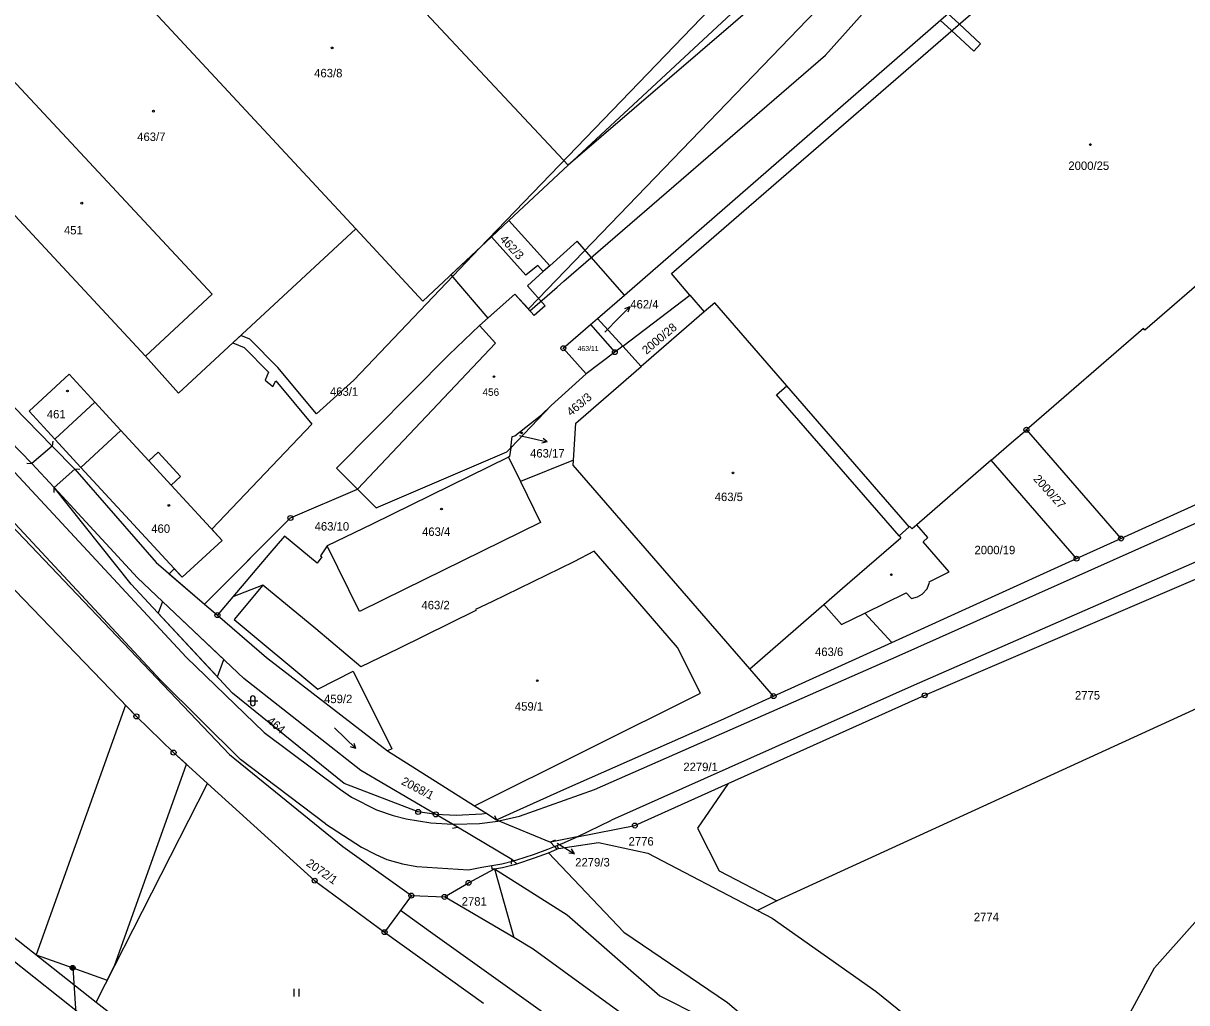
# Model space of a CAD drawing. Extents: x -504988 to -494607, y -1123820 to -1114018.
# Drawn here: x -496720.6 to -496486.2, y -1120850 to -1120652.7 of the extents above; entities that cross this region are included whole.
import ezdxf

# ---------------------------------------------------------------- set-up
doc = ezdxf.new("R2010")
doc.units = 0
for name, color, linetype in [('Hranice parcel', 7, 'Continuous'), ('Parcelní čísla', 7, 'Continuous'), ('Pop  PČ popisy', 7, 'Continuous'), ('Poz předměty', 7, 'Continuous'), ('Vnitřní kresba', 7, 'Continuous'), ('Věcná břemena k části', 7, 'Continuous'), ('Značky bodu BP', 7, 'Continuous'), ('Značky budov', 7, 'Continuous'), ('Značky kultur', 7, 'Continuous')]:
    doc.layers.add(name, color=color, linetype=linetype)

msp = doc.modelspace()

# ---------------------------------------------------------------- linework, layer by layer
at = {"layer": 'Hranice parcel'}
for p, q in [((-496599.45, -1120707.48), (-496501, -1120621.83)), ((-496610.77, -1120681.32), (-496661.37, -1120627.12)), ((-496736.91, -1120675.79), (-496695.94, -1120719.79)), ((-496610.77, -1120681.32), (-496622.74, -1120692.49)), ((-496622.74, -1120692.49), (-496626.2, -1120695.72)), ((-496622.74, -1120692.49), (-496614.48, -1120701.58)), ((-496640.08, -1120708.68), (-496653.59, -1120694.16)), ((-496626.2, -1120695.72), (-496640.08, -1120708.68)), ((-496614.48, -1120701.58), (-496615.79, -1120702.76)), ((-496604.86, -1120712.18), (-496599.45, -1120707.48)), ((-496599.79, -1120717.77), (-496586.26, -1120707.47)), ((-496586.26, -1120707.47), (-496583.37, -1120710.85)), ((-496583.37, -1120710.85), (-496596.06, -1120721.88)), ((-496606.31, -1120713.44), (-496604.86, -1120712.18)), ((-496606.31, -1120713.44), (-496601.38, -1120718.98)), ((-496599.79, -1120717.77), (-496604.86, -1120712.18)), ((-496601.38, -1120718.98), (-496607.13, -1120723.35)), ((-496599.79, -1120717.77), (-496601.38, -1120718.98)), ((-496596.06, -1120721.88), (-496599.79, -1120717.77)), ((-496614.22, -1120729.7), (-496607.13, -1120723.35)), ((-496542.87, -1120753.23), (-496566.72, -1120725.75)), ((-496614.22, -1120729.7), (-496622.37, -1120738.24)), ((-496616.13, -1120731.58), (-496614.22, -1120729.7)), ((-496499.4, -1120756.52), (-496439.9, -1120729.53)), ((-496700.9, -1120734.76), (-496708.96, -1120742.19)), ((-496521.45, -1120737.2), (-496518.46, -1120734.61)), ((-496518.46, -1120734.61), (-496499.4, -1120756.52)), ((-496714.72, -1120737.91), (-496710.16, -1120742.53)), ((-496525.56, -1120740.76), (-496521.45, -1120737.2)), ((-496622.62, -1120740.01), (-496622.79, -1120740.14)), ((-496622.79, -1120740.14), (-496620.39, -1120745.03)), ((-496622.37, -1120738.24), (-496622.62, -1120740.01)), ((-496714.32, -1120746.22), (-496718.88, -1120741.41)), ((-496609.72, -1120740.74), (-496620.39, -1120745.03)), ((-496525.56, -1120740.76), (-496540.53, -1120753.75)), ((-496508.34, -1120760.57), (-496525.56, -1120740.76)), ((-496508.34, -1120760.57), (-496499.4, -1120756.52)), ((-496652.84, -1120771.24), (-496659.35, -1120757.98)), ((-496670.9, -1120759.46), (-496678.32, -1120768.24)), ((-496545.59, -1120777.46), (-496508.34, -1120760.57)), ((-496672.33, -1120765.9), (-496678.32, -1120768.24)), ((-496678.32, -1120768.24), (-496680.54, -1120770.86)), ((-496435.15, -1120768.26), (-496568.75, -1120829.51)), ((-496550.98, -1120771.52), (-496542.65, -1120767.47)), ((-496684.03, -1120769.74), (-496681.46, -1120771.94)), ((-496574.21, -1120782.75), (-496559.3, -1120769.81)), ((-496559.3, -1120769.81), (-496555.71, -1120773.83)), ((-496680.54, -1120770.86), (-496681.46, -1120771.94)), ((-496555.71, -1120773.83), (-496550.98, -1120771.52)), ((-496545.59, -1120777.46), (-496550.98, -1120771.52)), ((-496569.39, -1120788.25), (-496545.59, -1120777.46)), ((-496569.39, -1120788.25), (-496574.21, -1120782.75)), ((-496647.2, -1120799.29), (-496629.63, -1120810.34)), ((-496705.9, -1120849.89), (-496683.43, -1120805.87)), ((-496760.7, -1120806.72), (-496705.9, -1120849.89)), ((-496622.14, -1120821.13), (-496633.09, -1120814.63)), ((-496608.94, -1120816.59), (-496614.32, -1120817.64)), ((-496614.74, -1120819.84), (-496613.04, -1120819.11)), ((-496613.04, -1120819.11), (-496612.72, -1120818.97)), ((-496625.66, -1120823.04), (-496621.76, -1120836.9)), ((-496642.38, -1120828.43), (-496647.77, -1120835.8)), ((-496642.38, -1120828.43), (-496635.69, -1120828.69)), ((-496621.76, -1120836.9), (-496635.69, -1120828.69)), ((-496568.75, -1120829.51), (-496572.66, -1120831.42)), ((-496647.77, -1120835.8), (-496627.83, -1120850.13))]:
    msp.add_line(p, q, dxfattribs=at)
for points in [[(-496576.2, -1120593.19), (-496572.35, -1120597.31), (-496590.77, -1120614.56), (-496589.81, -1120615.63), (-496589.91, -1120619.17), (-496586.4, -1120619.3), (-496583.79, -1120622.09), (-496583.86, -1120625.64), (-496580.35, -1120625.77), (-496577.76, -1120628.55), (-496577.86, -1120632.04), (-496574.29, -1120632.22), (-496566.73, -1120640.34), (-496610.77, -1120681.32)], [(-496653.59, -1120694.16), (-496706.72, -1120636.91), (-496707.61, -1120635.95)], [(-496586.26, -1120707.47), (-496589.96, -1120703.15), (-496514.17, -1120637.38), (-496507.54, -1120645.06)], [(-496718.88, -1120741.41), (-496755.05, -1120704.18), (-496797.4, -1120658.11)], [(-496789.1, -1120656), (-496791.3, -1120657.18), (-496753.93, -1120697.83), (-496714.72, -1120737.91)], [(-496695.94, -1120719.79), (-496682.54, -1120707.31), (-496723.77, -1120663.04), (-496737.17, -1120675.52)], [(-496467.67, -1120691.18), (-496480.14, -1120702.04), (-496494.59, -1120714.52), (-496494.88, -1120714.19), (-496518.46, -1120734.61)], [(-496653.59, -1120694.16), (-496689.31, -1120727.24), (-496695.94, -1120719.79)], [(-496615.79, -1120702.76), (-496616.91, -1120701.5), (-496619.32, -1120703.46), (-496626.2, -1120695.72)], [(-496599.45, -1120707.48), (-496608.97, -1120696.64), (-496614.48, -1120701.58)], [(-496615.79, -1120702.76), (-496619.01, -1120705.64), (-496615.45, -1120709.66), (-496617.64, -1120711.6)], [(-496617.64, -1120711.6), (-496621.52, -1120707.27), (-496628.62, -1120713.63), (-496634.8, -1120719.53)], [(-496566.72, -1120725.75), (-496581.25, -1120709.01), (-496583.37, -1120710.85)], [(-496607.13, -1120723.35), (-496611.76, -1120718.18), (-496606.31, -1120713.44)], [(-496634.8, -1120719.53), (-496657.48, -1120742.36), (-496653.26, -1120746.55)], [(-496700.9, -1120734.76), (-496706.13, -1120729.08), (-496711.34, -1120723.42), (-496719.41, -1120730.83), (-496714.19, -1120736.5), (-496708.96, -1120742.19)], [(-496609.72, -1120740.74), (-496609.21, -1120733.31), (-496596.06, -1120721.88)], [(-496622.37, -1120738.24), (-496622.04, -1120735.94), (-496621.53, -1120735.81), (-496616.13, -1120731.58)], [(-496680.53, -1120756.9), (-496690.8, -1120745.74), (-496688.91, -1120743.99), (-496693.41, -1120739.14), (-496695.27, -1120740.87), (-496700.9, -1120734.76)], [(-496736.43, -1120739.78), (-496679.03, -1120800.02), (-496656.16, -1120818.53), (-496642.38, -1120828.43)], [(-496622.79, -1120740.14), (-496650.3, -1120753.65), (-496659.35, -1120757.98)], [(-496653.26, -1120746.55), (-496649.47, -1120750.31), (-496623.13, -1120739.04), (-496622.37, -1120738.24)], [(-496710.16, -1120742.53), (-496693.8, -1120761.35), (-496684.03, -1120769.74)], [(-496708.96, -1120742.19), (-496688.59, -1120764.32), (-496680.53, -1120756.9)], [(-496574.21, -1120782.75), (-496609.79, -1120741.73), (-496609.72, -1120740.74)], [(-496578.55, -1120805.88), (-496538.95, -1120788.09), (-496442.52, -1120746.8), (-496429.62, -1120741.25)], [(-496637.46, -1120812.08), (-496652.57, -1120803.23), (-496676.15, -1120784.7), (-496697.59, -1120764.44), (-496714.32, -1120746.22)], [(-496637.46, -1120812.08), (-496637.86, -1120812.05), (-496641.01, -1120811.58), (-496655.93, -1120805.84), (-496678.43, -1120787.63), (-496698.84, -1120765.71), (-496714.32, -1120746.22)], [(-496684.03, -1120769.74), (-496682.96, -1120768.68), (-496666.75, -1120752.38), (-496653.26, -1120746.55)], [(-496620.39, -1120745.03), (-496616.33, -1120753.28), (-496643.83, -1120766.78), (-496652.84, -1120771.24)], [(-496541.92, -1120754.06), (-496542.05, -1120754.17), (-496542.87, -1120753.23)], [(-496542.65, -1120767.47), (-496541.63, -1120768.59), (-496540.41, -1120768.28), (-496539.43, -1120767.7), (-496538.48, -1120766.62), (-496537.97, -1120765.39), (-496538.07, -1120765.22), (-496533.99, -1120763.22), (-496539.27, -1120757.16), (-496538.29, -1120756.33), (-496540.53, -1120753.75)], [(-496540.53, -1120753.75), (-496541.48, -1120754.58), (-496541.92, -1120754.06)], [(-496659.35, -1120757.98), (-496660.68, -1120759.98), (-496660.4, -1120760.21), (-496661.37, -1120761.45), (-496667.95, -1120756.02), (-496670.9, -1120759.46)], [(-496730.97, -1120757.93), (-496725.74, -1120763.35), (-496697.78, -1120792.34), (-496690.3, -1120799.63), (-496683.43, -1120805.87)], [(-496629.63, -1120810.34), (-496584.12, -1120787.67), (-496588.73, -1120778.45), (-496595.45, -1120770.65), (-496605.54, -1120759.06), (-496609.63, -1120761.18), (-496626.17, -1120769.27), (-496629.46, -1120770.83), (-496629.38, -1120771.01), (-496645.05, -1120778.75), (-496652.55, -1120782.38), (-496661.64, -1120774.72), (-496672.33, -1120765.9)], [(-496672.33, -1120765.9), (-496678.08, -1120772.84), (-496661.22, -1120786.83), (-496654.09, -1120783.25), (-496646.34, -1120798.86), (-496647.2, -1120799.29)], [(-496681.46, -1120771.94), (-496671.55, -1120780.45), (-496647.2, -1120799.29)], [(-496572.66, -1120831.42), (-496569.68, -1120832.98), (-496548.73, -1120847.78), (-496521.28, -1120869.97), (-496513.63, -1120873.99), (-496508.49, -1120871.39), (-496505.53, -1120866.79), (-496492.64, -1120843.01), (-496469.33, -1120816.78), (-496459.79, -1120808.55), (-496450.03, -1120793.69), (-496441, -1120785.01)], [(-496625.22, -1120813.19), (-496611.64, -1120807.04), (-496580.04, -1120793.08), (-496569.39, -1120788.25)], [(-496683.43, -1120805.87), (-496677.02, -1120811.68), (-496661.86, -1120825.43), (-496647.77, -1120835.8)], [(-496608.94, -1120816.59), (-496597.35, -1120814.33), (-496578.55, -1120805.88)], [(-496578.55, -1120805.88), (-496584.7, -1120814.82), (-496580.39, -1120823.43), (-496568.75, -1120829.51)], [(-496652.07, -1120896.36), (-496660.77, -1120890.4), (-496670.34, -1120882.59), (-496708.65, -1120852.67), (-496762.64, -1120809.83)], [(-496629.63, -1120810.34), (-496627.17, -1120811.93), (-496625.22, -1120813.19)], [(-496633.09, -1120814.63), (-496634.09, -1120814.04), (-496637.46, -1120812.08)], [(-496625.22, -1120813.19), (-496624.73, -1120813.39), (-496614.32, -1120817.64)], [(-496614.32, -1120817.64), (-496613.54, -1120818.54), (-496613.04, -1120819.11)], [(-496612.72, -1120818.97), (-496613.01, -1120818.33), (-496611.55, -1120817.73), (-496608.94, -1120816.59)], [(-496621.12, -1120822.03), (-496617.58, -1120820.83), (-496614.74, -1120819.84)], [(-496614.74, -1120819.84), (-496599.55, -1120835.82), (-496578.68, -1120849.97), (-496555.07, -1120870.01), (-496514.99, -1120901.27), (-496501.68, -1120912.44), (-496491.84, -1120918.22), (-496488.07, -1120918.8)], [(-496612.72, -1120818.97), (-496604.65, -1120817.71), (-496594.71, -1120819.9), (-496572.66, -1120831.42)], [(-496625.66, -1120823.04), (-496624.02, -1120822.75), (-496621.88, -1120822.22), (-496621.12, -1120822.03)], [(-496621.12, -1120822.03), (-496621.83, -1120821.4), (-496622.14, -1120821.13)], [(-496635.69, -1120828.69), (-496630.86, -1120825.86), (-496625.66, -1120823.04)], [(-496625.66, -1120823.04), (-496610.99, -1120832.3), (-496592.3, -1120848.59), (-496584.08, -1120852.81), (-496507.4, -1120915.64), (-496489.64, -1120926.7)], [(-496550.64, -1120888.17), (-496617.81, -1120839.23), (-496621.76, -1120836.9)], [(-496705.9, -1120849.89), (-496667.6, -1120879.73), (-496652.46, -1120890.72), (-496647.86, -1120890.04)]]:
    msp.add_lwpolyline(points, dxfattribs=at)
at = {"layer": 'Pop  PČ popisy'}
for p, q in [((-496603.43, -1120714.92), (-496600.5, -1120711.99)), ((-496600.5, -1120711.99), (-496598.38, -1120709.87)), ((-496598.38, -1120709.87), (-496599.44, -1120710.22)), ((-496598.38, -1120709.87), (-496598.73, -1120710.93)), ((-496620.57, -1120735.76), (-496617.91, -1120736.39)), ((-496617.91, -1120736.39), (-496614.99, -1120737.06)), ((-496614.99, -1120737.06), (-496616.07, -1120737.33)), ((-496614.99, -1120737.06), (-496615.85, -1120736.35)), ((-496613.01, -1120817.9), (-496612.1, -1120818.44)), ((-496612.1, -1120818.44), (-496609.53, -1120819.99)), ((-496609.53, -1120819.99), (-496610.64, -1120819.9)), ((-496609.53, -1120819.99), (-496610.13, -1120819.04))]:
    msp.add_line(p, q, dxfattribs=at)
at = {"layer": 'Poz předměty'}
for p, q in [((-496638.49, -1120835.81), (-496644.58, -1120831.44)), ((-496601.7, -1120862.03), (-496638.49, -1120835.81)), ((-496710.62, -1120842.99), (-496703.98, -1120937.52))]:
    msp.add_line(p, q, dxfattribs=at)
for radius in [0.5, 0.4, 0.3, 0.2, 0.1]:
    msp.add_circle((-496710.62, -1120842.99), radius, dxfattribs=at)
at = {"layer": 'Vnitřní kresba'}
for p, q in [((-496568.82, -1120727.58), (-496566.72, -1120725.75)), ((-496544.11, -1120755.99), (-496568.82, -1120727.58)), ((-496706.13, -1120729.08), (-496714.19, -1120736.5)), ((-496544.11, -1120780.08), (-496433.36, -1120730.69)), ((-496729.32, -1120735.69), (-496687.78, -1120780.42)), ((-496714.72, -1120737.91), (-496718.88, -1120741.41)), ((-496714.63, -1120736.91), (-496714.72, -1120737.91)), ((-496430.3, -1120737.64), (-496541.1, -1120786.05)), ((-496692.92, -1120785.07), (-496734.84, -1120740.03)), ((-496719.88, -1120741.32), (-496718.88, -1120741.41)), ((-496710.16, -1120742.53), (-496714.32, -1120746.22)), ((-496709.16, -1120742.58), (-496710.16, -1120742.53)), ((-496695.27, -1120740.87), (-496690.8, -1120745.74)), ((-496714.37, -1120747.22), (-496714.32, -1120746.22)), ((-496542.05, -1120754.17), (-496544.11, -1120755.99)), ((-496555.51, -1120766.53), (-496543.79, -1120756.36)), ((-496544.11, -1120755.99), (-496543.79, -1120756.36)), ((-496559.3, -1120769.81), (-496555.51, -1120766.53)), ((-496605.47, -1120807.08), (-496544.11, -1120780.08)), ((-496687.78, -1120780.42), (-496672.07, -1120795.58)), ((-496541.1, -1120786.05), (-496602.05, -1120813.24)), ((-496672.07, -1120795.58), (-496656.67, -1120807.08)), ((-496625.61, -1120812.27), (-496625.22, -1120813.19)), ((-496634.06, -1120814.87), (-496633.09, -1120814.63)), ((-496608.94, -1120816.59), (-496602.05, -1120813.24)), ((-496613.4, -1120817.25), (-496614.32, -1120817.64)), ((-496614.86, -1120819.05), (-496613.54, -1120818.54)), ((-496613.54, -1120818.54), (-496613.01, -1120818.33)), ((-496622.23, -1120822.13), (-496622.14, -1120821.13))]:
    msp.add_line(p, q, dxfattribs=at)
for points in [[(-496659.65, -1120813.99), (-496676.79, -1120801.02), (-496692.92, -1120785.07)], [(-496656.67, -1120807.08), (-496654.43, -1120808.59), (-496649.42, -1120811.14), (-496646.06, -1120812.28), (-496643.43, -1120812.96), (-496638.44, -1120813.79), (-496634.09, -1120814.04)], [(-496624.73, -1120813.39), (-496620.61, -1120812.43), (-496605.47, -1120807.08)], [(-496627.17, -1120811.93), (-496628.18, -1120812.02), (-496633.37, -1120812.33), (-496637.46, -1120812.08)], [(-496659.65, -1120813.99), (-496652.4, -1120818.67), (-496649.54, -1120820.17), (-496647.3, -1120821.14), (-496644.18, -1120822.05)], [(-496634.09, -1120814.04), (-496633.66, -1120814.07), (-496628.68, -1120813.92), (-496624.95, -1120813.44), (-496624.73, -1120813.39)], [(-496621.83, -1120821.4), (-496621.12, -1120821.21), (-496617.79, -1120820.13), (-496614.86, -1120819.05)], [(-496644.18, -1120822.05), (-496641.31, -1120822.58), (-496630.89, -1120823.25)], [(-496630.89, -1120823.25), (-496628.17, -1120822.69), (-496626.15, -1120822.34)], [(-496626.15, -1120822.34), (-496624.13, -1120822.03), (-496621.83, -1120821.4)], [(-496625.66, -1120823.04), (-496626.12, -1120823.12), (-496626.15, -1120822.34)]]:
    msp.add_lwpolyline(points, dxfattribs=at)
at = {"layer": 'Věcná břemena k části'}
for points in [[(-496570.87, -1120647.04), (-496610.77, -1120681.32), (-496622.74, -1120692.49), (-496614.48, -1120701.58), (-496615.79, -1120702.76), (-496616.91, -1120701.5), (-496619.32, -1120703.46), (-496626.2, -1120695.72), (-496634.45, -1120703.43), (-496626.94, -1120712.12), (-496621.52, -1120707.27), (-496618.5, -1120710.64), (-496613.01, -1120705.9), (-496611.64, -1120704.71), (-496558.93, -1120659.18), (-496513.93, -1120608.79)], [(-496567.98, -1120635.07), (-496628.65, -1120698), (-496653.99, -1120724.61), (-496661.52, -1120731.43), (-496669.3, -1120722.1), (-496674.91, -1120716.37), (-496676.75, -1120715.61), (-496678.36, -1120717.1), (-496676.05, -1120718.06), (-496671.18, -1120723.04), (-496671.81, -1120724.61), (-496670.29, -1120725.91), (-496669.68, -1120724.78), (-496662.41, -1120733.47), (-496682.57, -1120754.65), (-496680.53, -1120756.9), (-496688.59, -1120764.32), (-496690.17, -1120762.6), (-496691.15, -1120763.63), (-496684.03, -1120769.74), (-496666.75, -1120752.38), (-496653.26, -1120746.55), (-496625.4, -1120717.19), (-496628.62, -1120713.63), (-496621.52, -1120707.27), (-496618.81, -1120710.27), (-496616.78, -1120708.16), (-496546.34, -1120635.09)], [(-496535.81, -1120652.11), (-496533.55, -1120654.2), (-496529.07, -1120658.36), (-496527.71, -1120656.9), (-496532.03, -1120652.88), (-496534.29, -1120650.79)]]:
    msp.add_lwpolyline(points, dxfattribs=at)
for points in [[(-496614.48, -1120701.58), (-496615.79, -1120702.76), (-496616.91, -1120701.5), (-496619.32, -1120703.46), (-496626.2, -1120695.72), (-496622.74, -1120692.49)], [(-496692.53, -1120769.22), (-496693.38, -1120771.58), (-496681.44, -1120784.4), (-496680.18, -1120780.89)], [(-496690.3, -1120799.63), (-496697.78, -1120792.34), (-496699.98, -1120790.06), (-496717.95, -1120840.36), (-496710.62, -1120842.99), (-496703.64, -1120845.46), (-496702.18, -1120842.61), (-496687.7, -1120801.99)]]:
    msp.add_lwpolyline(points, close=True, dxfattribs=at)
at = {"layer": 'Značky bodu BP'}
for centre, radius in [((-496611.76, -1120718.18), 0.5), ((-496611.76, -1120718.18), 0.0303), ((-496601.38, -1120718.98), 0.5), ((-496601.38, -1120718.98), 0.0303), ((-496518.46, -1120734.61), 0.5), ((-496518.46, -1120734.61), 0.0303), ((-496666.75, -1120752.38), 0.5), ((-496666.75, -1120752.38), 0.0303), ((-496499.4, -1120756.52), 0.5), ((-496499.4, -1120756.52), 0.0303), ((-496508.34, -1120760.57), 0.5), ((-496508.34, -1120760.57), 0.0303), ((-496681.46, -1120771.94), 0.5), ((-496681.46, -1120771.94), 0.0303), ((-496569.39, -1120788.25), 0.5), ((-496569.39, -1120788.25), 0.0303), ((-496538.95, -1120788.09), 0.5), ((-496538.95, -1120788.09), 0.0303), ((-496697.78, -1120792.34), 0.5), ((-496697.78, -1120792.34), 0.0303), ((-496690.3, -1120799.63), 0.5), ((-496690.3, -1120799.63), 0.0303), ((-496641.01, -1120811.58), 0.5), ((-496641.01, -1120811.58), 0.0303), ((-496637.46, -1120812.08), 0.5), ((-496637.46, -1120812.08), 0.0303), ((-496597.35, -1120814.33), 0.5), ((-496597.35, -1120814.33), 0.0303), ((-496661.86, -1120825.43), 0.5), ((-496661.86, -1120825.43), 0.0303), ((-496630.86, -1120825.86), 0.5), ((-496630.86, -1120825.86), 0.0303), ((-496642.38, -1120828.43), 0.5), ((-496642.38, -1120828.43), 0.0303), ((-496635.69, -1120828.69), 0.5), ((-496635.69, -1120828.69), 0.0303), ((-496647.77, -1120835.8), 0.5), ((-496647.77, -1120835.8), 0.0303)]:
    msp.add_circle(centre, radius, dxfattribs=at)
at = {"layer": 'Značky budov'}
for centre in [(-496658.35, -1120657.7), (-496694.35, -1120670.44), (-496505.57, -1120677.16), (-496708.79, -1120688.97), (-496625.72, -1120723.91), (-496711.68, -1120726.81), (-496620.15, -1120735.25), (-496577.57, -1120743.3), (-496691.23, -1120749.85), (-496636.31, -1120750.57), (-496545.67, -1120763.8), (-496617, -1120785.15)]:
    msp.add_circle(centre, 0.175, dxfattribs=at)
at = {"layer": 'Značky kultur'}
for p, q in [((-496675.32, -1120789.21), (-496673.32, -1120789.21)), ((-496674.82, -1120788.71), (-496674.82, -1120789.71)), ((-496673.82, -1120789.71), (-496673.82, -1120788.71)), ((-496657.88, -1120794.64), (-496653.57, -1120798.81)), ((-496653.57, -1120798.81), (-496654.62, -1120798.49)), ((-496653.57, -1120798.81), (-496653.92, -1120797.77)), ((-496666, -1120848.73), (-496666, -1120847.23)), ((-496665, -1120848.73), (-496665, -1120847.23))]:
    msp.add_line(p, q, dxfattribs=at)
for centre, start, end in [((-496674.32, -1120788.71), 0, 180), ((-496674.32, -1120789.71), 180, 359.9879)]:
    msp.add_arc(centre, 0.5, start, end, dxfattribs=at)

# ---------------------------------------------------------------- texts
at = {"layer": 'Parcelní čísla'}
for s, height, p in [('463/8', 1.7, (-496661.96, -1120663.62)), ('463/7', 1.7, (-496697.62, -1120676.45)), ('2000/25', 1.7, (-496510, -1120682.28)), ('451', 1.7, (-496712.38, -1120695.26)), ('462/4', 1.7, (-496598.27, -1120710.18)), ('463/11', 1, (-496608.88, -1120718.75)), ('463/1', 1.7, (-496658.78, -1120727.77)), ('456', 1.5, (-496628.04, -1120727.77)), ('461', 1.7, (-496715.83, -1120732.32)), ('463/17', 1.7, (-496618.46, -1120740.2)), ('463/5', 1.7, (-496581.26, -1120748.97)), ('460', 1.7, (-496694.79, -1120755.37)), ('463/10', 1.7, (-496661.87, -1120754.91)), ('463/4', 1.7, (-496640.23, -1120755.99)), ('2000/19', 1.7, (-496528.92, -1120759.68)), ('463/2', 1.7, (-496640.34, -1120770.77)), ('463/6', 1.7, (-496561.05, -1120780.18)), ('459/2', 1.7, (-496659.97, -1120789.67)), ('459/1', 1.7, (-496621.52, -1120791.18)), ('2775', 1.7, (-496508.67, -1120788.94)), ('2279/1', 1.7, (-496587.58, -1120803.36)), ('2776', 1.7, (-496598.61, -1120818.36)), ('2279/3', 1.7, (-496609.36, -1120822.57)), ('2781', 1.7, (-496632.24, -1120830.45)), ('2774', 1.7, (-496529.05, -1120833.59))]:
    msp.add_text(s, height=height, dxfattribs=at).set_placement(p)
for s, rotation, p in [('462/3', 313, (-496624.68, -1120696.34)), ('2000/28', 40, (-496595.01, -1120719.53)), ('463/3', 40, (-496610.22, -1120731.96)), ('2000/27', 312, (-496517.17, -1120744.58)), ('464', 320, (-496671.59, -1120793.51)), ('2068/1', 332, (-496644.55, -1120805.93)), ('2072/1', 325, (-496663.71, -1120822.28))]:
    msp.add_text(s, height=1.7, rotation=rotation, dxfattribs=at).set_placement(p)

doc.saveas('drawing.dxf')
